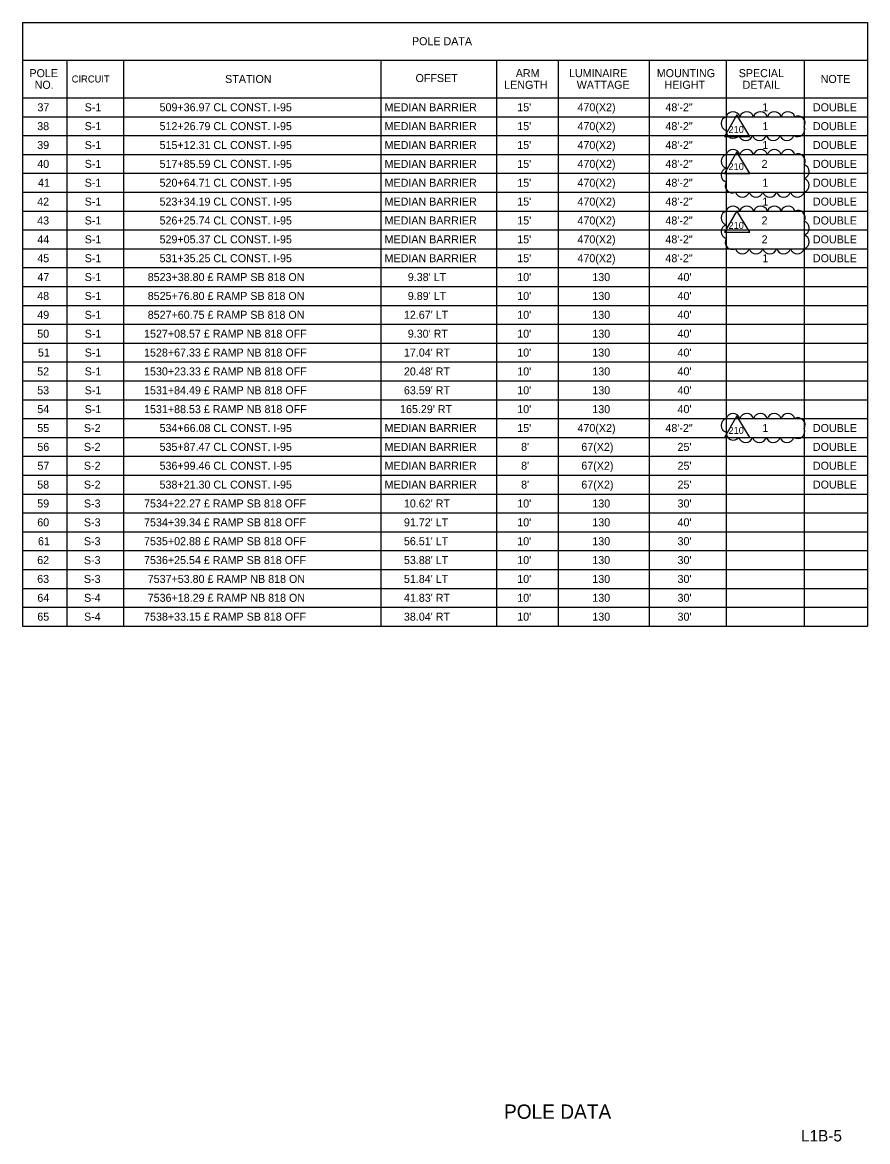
# Model space of a CAD drawing. Extents: x -816.7 to -800.7, y -2197.9 to -2187.9.
# Drawn here: x -808.09 to -800.7, y -2197.64 to -2187.86 of the extents above; entities that cross this region are included whole.
import ezdxf

# ---------------------------------------------------------------- set-up
doc = ezdxf.new("R2010")
doc.units = 0
for name, color, linetype in [('ScratchEle_dp', 7, 'Continuous'), ('SumBoxBorder_dp', 7, 'Continuous'), ('SumBoxLines_dp', 7, 'Continuous'), ('SumBoxLinesMin_dp', 7, 'Continuous'), ('TextLabel', 7, 'Continuous'), ('TextMisc', 7, 'Continuous'), ('TextShtNo', 7, 'Continuous')]:
    doc.layers.add(name, color=color, linetype=linetype)

msp = doc.modelspace()

# ---------------------------------------------------------------- linework, layer by layer
at = {"layer": 'ScratchEle_dp'}
for points in [[(-801.8411, -2188.6653), (-801.9488, -2188.8534), (-801.7282, -2188.8534)], [(-801.8411, -2188.9897), (-801.9488, -2189.1778), (-801.7282, -2189.1778)], [(-801.8411, -2189.504), (-801.9488, -2189.6921), (-801.7282, -2189.6921)], [(-801.8411, -2191.2972), (-801.9488, -2191.4853), (-801.7282, -2191.4853)]]:
    msp.add_lwpolyline(points, close=True, dxfattribs=at)
for centre, radius, start, end in [((-801.8748, -2188.7001), 0.0629, 17.5, 162.5), ((-801.7548, -2188.7001), 0.0629, 17.5, 162.5), ((-801.6348, -2188.7001), 0.0629, 17.5, 162.5), ((-801.5147, -2188.7001), 0.0629, 17.5, 162.5), ((-801.3947, -2188.7001), 0.0629, 17.5, 162.5), ((-801.9159, -2188.7412), 0.0629, 107.5, 252.5), ((-801.3073, -2188.7378), 0.0629, 330.87934, 115.87934), ((-801.8721, -2188.8062), 0.0629, 175.48211, 320.48211), ((-801.3102, -2188.7929), 0.0629, 237.99061, 22.99061), ((-801.7636, -2188.8273), 0.0629, 197.5, 342.5), ((-801.6436, -2188.8273), 0.0629, 197.5, 342.5), ((-801.5236, -2188.8273), 0.0629, 197.5, 342.5), ((-801.4035, -2188.8273), 0.0629, 197.5, 342.5), ((-801.9159, -2189.0714), 0.0631, 107.5, 252.5), ((-801.8747, -2189.0302), 0.0631, 17.5, 162.5), ((-801.7543, -2189.0302), 0.0631, 17.5, 162.5), ((-801.6339, -2189.0302), 0.0631, 17.5, 162.5), ((-801.5136, -2189.0302), 0.0631, 17.5, 162.5), ((-801.3932, -2189.0302), 0.0631, 17.5, 162.5), ((-801.3067, -2189.0686), 0.0631, 329.60153, 114.60153), ((-801.2713, -2189.1607), 0.0631, 287.5, 72.5), ((-801.9159, -2189.1918), 0.0631, 107.5, 252.5), ((-801.2713, -2189.281), 0.0631, 287.5, 72.5), ((-801.8804, -2189.2839), 0.0631, 149.60153, 294.60153), ((-801.794, -2189.3222), 0.0631, 197.5, 342.5), ((-801.6736, -2189.3222), 0.0631, 197.5, 342.5), ((-801.5533, -2189.3222), 0.0631, 197.5, 342.5), ((-801.4329, -2189.3222), 0.0631, 197.5, 342.5), ((-801.3125, -2189.3222), 0.0631, 197.5, 342.5), ((-801.9159, -2189.5664), 0.0631, 107.5, 252.5), ((-801.8747, -2189.5252), 0.0631, 17.5, 162.5), ((-801.7543, -2189.5252), 0.0631, 17.5, 162.5), ((-801.6339, -2189.5252), 0.0631, 17.5, 162.5), ((-801.5136, -2189.5252), 0.0631, 17.5, 162.5), ((-801.3932, -2189.5252), 0.0631, 17.5, 162.5), ((-801.3067, -2189.5636), 0.0631, 329.60153, 114.60153), ((-801.2713, -2189.6557), 0.0631, 287.5, 72.5), ((-801.9159, -2189.6868), 0.0631, 107.5, 252.5), ((-801.2713, -2189.776), 0.0631, 287.5, 72.5), ((-801.8804, -2189.7789), 0.0631, 149.60153, 294.60153), ((-801.794, -2189.8172), 0.0631, 197.5, 342.5), ((-801.6736, -2189.8172), 0.0631, 197.5, 342.5), ((-801.5533, -2189.8172), 0.0631, 197.5, 342.5), ((-801.4329, -2189.8172), 0.0631, 197.5, 342.5), ((-801.3125, -2189.8172), 0.0631, 197.5, 342.5), ((-801.8748, -2191.3401), 0.0629, 17.5, 162.5), ((-801.7548, -2191.3401), 0.0629, 17.5, 162.5), ((-801.6348, -2191.3401), 0.0629, 17.5, 162.5), ((-801.5147, -2191.3401), 0.0629, 17.5, 162.5), ((-801.3947, -2191.3401), 0.0629, 17.5, 162.5), ((-801.9159, -2191.3812), 0.0629, 107.5, 252.5), ((-801.3073, -2191.3778), 0.0629, 330.87934, 115.87934), ((-801.8721, -2191.4462), 0.0629, 175.48211, 320.48211), ((-801.3102, -2191.4329), 0.0629, 237.99061, 22.99061), ((-801.7636, -2191.4673), 0.0629, 197.5, 342.5), ((-801.6436, -2191.4673), 0.0629, 197.5, 342.5), ((-801.5236, -2191.4673), 0.0629, 197.5, 342.5), ((-801.4035, -2191.4673), 0.0629, 197.5, 342.5)]:
    msp.add_arc(centre, radius, start, end, dxfattribs=at)
at = {"layer": 'SumBoxBorder_dp'}
for p, q in [((-808.0923, -2187.8562), (-800.6973, -2187.8562)), ((-808.0923, -2187.8562), (-808.0923, -2193.1362)), ((-800.6973, -2187.8562), (-800.6973, -2193.1362)), ((-808.0923, -2188.1862), (-800.6973, -2188.1862)), ((-808.0923, -2188.1862), (-800.6973, -2188.1862)), ((-808.0923, -2193.1362), (-800.6973, -2193.1362)), ((-808.0923, -2193.1362), (-800.6973, -2193.1362))]:
    msp.add_line(p, q, dxfattribs=at)
at = {"layer": 'SumBoxLines_dp'}
for p, q in [((-807.7023, -2188.1862), (-807.7023, -2193.1362)), ((-807.7023, -2188.1862), (-807.7023, -2193.1362)), ((-807.2073, -2188.1862), (-807.2073, -2191.9812)), ((-807.2073, -2188.1862), (-807.2073, -2193.1362)), ((-804.9573, -2188.1862), (-804.9573, -2191.4862)), ((-804.9573, -2188.1862), (-804.9573, -2193.1362)), ((-803.9448, -2188.1862), (-803.9448, -2193.1362)), ((-803.9448, -2188.1862), (-803.9448, -2193.1362)), ((-803.4048, -2188.1862), (-803.4048, -2191.9812)), ((-803.4048, -2188.1862), (-803.4048, -2193.1362)), ((-802.6098, -2188.1862), (-802.6098, -2193.1362)), ((-802.6098, -2188.1862), (-802.6098, -2193.1362)), ((-801.9348, -2188.1862), (-801.9348, -2193.1362)), ((-801.9348, -2188.1862), (-801.9348, -2193.1362)), ((-801.2523, -2188.1862), (-801.2523, -2193.1362)), ((-808.0923, -2188.5162), (-800.6973, -2188.5162)), ((-804.9573, -2191.6512), (-804.9573, -2193.1362)), ((-807.2073, -2192.1462), (-807.2073, -2192.3112)), ((-803.4048, -2192.1462), (-803.4048, -2193.1362)), ((-807.2073, -2192.4762), (-807.2073, -2192.6412)), ((-807.2073, -2192.8062), (-807.2073, -2193.1362))]:
    msp.add_line(p, q, dxfattribs=at)
at = {"layer": 'SumBoxLinesMin_dp'}
for p, q in [((-808.0923, -2188.5162), (-800.6973, -2188.5162)), ((-808.0923, -2188.6812), (-800.6973, -2188.6812)), ((-808.0923, -2188.6812), (-800.6973, -2188.6812)), ((-808.0923, -2188.8462), (-800.6973, -2188.8462)), ((-808.0923, -2188.8462), (-800.6973, -2188.8462)), ((-808.0923, -2189.0112), (-800.6973, -2189.0112)), ((-808.0923, -2189.0112), (-800.6973, -2189.0112)), ((-808.0923, -2189.1762), (-800.6973, -2189.1762)), ((-808.0923, -2189.1762), (-800.6973, -2189.1762)), ((-808.0923, -2189.3412), (-800.6973, -2189.3412)), ((-808.0923, -2189.3412), (-800.6973, -2189.3412)), ((-808.0923, -2189.5062), (-800.6973, -2189.5062)), ((-808.0923, -2189.5062), (-800.6973, -2189.5062)), ((-808.0923, -2189.6712), (-800.6973, -2189.6712)), ((-808.0923, -2189.6712), (-800.6973, -2189.6712)), ((-808.0923, -2189.8362), (-800.6973, -2189.8362)), ((-808.0923, -2189.8362), (-800.6973, -2189.8362)), ((-808.0923, -2190.0012), (-800.6973, -2190.0012)), ((-808.0923, -2190.0012), (-800.6973, -2190.0012)), ((-808.0923, -2190.1662), (-800.6973, -2190.1662)), ((-808.0923, -2190.1662), (-800.6973, -2190.1662)), ((-808.0923, -2190.3312), (-800.6973, -2190.3312)), ((-808.0923, -2190.3312), (-800.6973, -2190.3312)), ((-808.0923, -2190.4962), (-800.6973, -2190.4962)), ((-808.0923, -2190.4962), (-800.6973, -2190.4962)), ((-808.0923, -2190.6612), (-800.6973, -2190.6612)), ((-808.0923, -2190.6612), (-800.6973, -2190.6612)), ((-808.0923, -2190.8262), (-800.6973, -2190.8262)), ((-808.0923, -2190.8262), (-800.6973, -2190.8262)), ((-808.0923, -2190.9912), (-800.6973, -2190.9912)), ((-808.0923, -2190.9912), (-800.6973, -2190.9912)), ((-808.0923, -2191.1562), (-800.6973, -2191.1562)), ((-808.0923, -2191.1562), (-800.6973, -2191.1562)), ((-808.0923, -2191.3212), (-800.6973, -2191.3212)), ((-808.0923, -2191.3212), (-800.6973, -2191.3212)), ((-808.0923, -2191.4862), (-800.6973, -2191.4862)), ((-808.0923, -2191.4862), (-800.6973, -2191.4862)), ((-808.0923, -2191.6512), (-807.2073, -2191.6512)), ((-808.0923, -2191.6512), (-800.6973, -2191.6512)), ((-804.9573, -2191.6512), (-800.6973, -2191.6512)), ((-808.0923, -2191.8162), (-800.6973, -2191.8162)), ((-808.0923, -2191.8162), (-800.6973, -2191.8162)), ((-808.0923, -2191.9812), (-800.6973, -2191.9812)), ((-808.0923, -2191.9812), (-800.6973, -2191.9812)), ((-808.0923, -2192.1462), (-807.7023, -2192.1462)), ((-808.0923, -2192.1462), (-800.6973, -2192.1462)), ((-807.2073, -2192.1462), (-803.9448, -2192.1462)), ((-803.4048, -2192.1462), (-800.6973, -2192.1462)), ((-808.0923, -2192.3112), (-800.6973, -2192.3112)), ((-808.0923, -2192.3112), (-800.6973, -2192.3112)), ((-808.0923, -2192.4762), (-807.7023, -2192.4762)), ((-808.0923, -2192.4762), (-800.6973, -2192.4762)), ((-804.9573, -2192.4762), (-800.6973, -2192.4762)), ((-808.0923, -2192.6412), (-800.6973, -2192.6412)), ((-808.0923, -2192.6412), (-800.6973, -2192.6412)), ((-808.0923, -2192.8062), (-807.7023, -2192.8062)), ((-808.0923, -2192.8062), (-800.6973, -2192.8062)), ((-804.9573, -2192.8062), (-800.6973, -2192.8062)), ((-808.0923, -2192.9712), (-800.6973, -2192.9712)), ((-808.0923, -2192.9712), (-800.6973, -2192.9712))]:
    msp.add_line(p, q, dxfattribs=at)

# ---------------------------------------------------------------- texts
at = {"layer": 'ScratchEle_dp'}
for p in [(-801.9143, -2188.8232), (-801.9143, -2189.1477), (-801.9143, -2189.6619), (-801.9143, -2191.4552)]:
    msp.add_text('210', height=0.05998, rotation=0, dxfattribs=at).set_placement(p)
at = {"layer": 'TextLabel'}
for s, height, p in [('POLE DATA', 0.07, (-804.6838, -2188.0562)), ('POLE', 0.07, (-808.0306, -2188.3352)), ('CIRCUIT', 0.06125, (-807.6608, -2188.3818)), ('STATION', 0.07, (-806.3182, -2188.3862)), ('OFFSET', 0.07, (-804.6526, -2188.3782)), ('ARM', 0.07, (-803.7754, -2188.3352)), ('LUMINAIRE', 0.07, (-803.31, -2188.3352)), ('MOUNTING', 0.07, (-802.542, -2188.3352)), ('SPECIAL', 0.07, (-801.825, -2188.3352)), ('NOTE', 0.07, (-801.1081, -2188.3862)), ('NO.', 0.07, (-807.985, -2188.4372)), ('LENGTH', 0.07, (-803.8768, -2188.4372)), ('WATTAGE', 0.07, (-803.2423, -2188.4372)), ('HEIGHT', 0.07, (-802.4738, -2188.4372)), ('DETAIL', 0.07, (-801.7911, -2188.4372)), ('37', 0.07, (-807.9606, -2188.6337)), ('S-1', 0.07, (-807.5473, -2188.6337)), ('509+36.97 CL CONST. I-95', 0.07, (-806.8921, -2188.6337)), ('MEDIAN BARRIER', 0.07, (-804.9232, -2188.6337)), ("15'", 0.07, (-803.7628, -2188.6337)), ('470(X2)', 0.07, (-803.2358, -2188.6337)), ('48\'-2"', 0.07, (-802.4663, -2188.6337)), ('1', 0.07, (-801.6183, -2188.6337)), ('DOUBLE', 0.07, (-801.1759, -2188.6337)), ('38', 0.07, (-807.9624, -2188.7987)), ('S-1', 0.07, (-807.5473, -2188.7987)), ('512+26.79 CL CONST. I-95', 0.07, (-806.8921, -2188.7987)), ('MEDIAN BARRIER', 0.07, (-804.9232, -2188.7987)), ("15'", 0.07, (-803.7628, -2188.7987)), ('470(X2)', 0.07, (-803.2358, -2188.7987)), ('48\'-2"', 0.07, (-802.4663, -2188.7987)), ('1', 0.07, (-801.6183, -2188.7987)), ('DOUBLE', 0.07, (-801.1759, -2188.7987)), ('39', 0.07, (-807.9622, -2188.9637)), ('S-1', 0.07, (-807.5473, -2188.9637)), ('515+12.31 CL CONST. I-95', 0.07, (-806.8921, -2188.9637)), ('MEDIAN BARRIER', 0.07, (-804.9232, -2188.9637)), ("15'", 0.07, (-803.7628, -2188.9637)), ('470(X2)', 0.07, (-803.2358, -2188.9637)), ('48\'-2"', 0.07, (-802.4663, -2188.9637)), ('1', 0.07, (-801.6183, -2188.9637)), ('DOUBLE', 0.07, (-801.1759, -2188.9637)), ('40', 0.07, (-807.9621, -2189.1287)), ('S-1', 0.07, (-807.5473, -2189.1287)), ('517+85.59 CL CONST. I-95', 0.07, (-806.8921, -2189.1287)), ('MEDIAN BARRIER', 0.07, (-804.9232, -2189.1287)), ("15'", 0.07, (-803.7628, -2189.1287)), ('470(X2)', 0.07, (-803.2358, -2189.1287)), ('48\'-2"', 0.07, (-802.4663, -2189.1287)), ('2', 0.07, (-801.625, -2189.1287)), ('DOUBLE', 0.07, (-801.1759, -2189.1287)), ('41', 0.07, (-807.9559, -2189.2937)), ('S-1', 0.07, (-807.5473, -2189.2937)), ('520+64.71 CL CONST. I-95', 0.07, (-806.8921, -2189.2937)), ('MEDIAN BARRIER', 0.07, (-804.9232, -2189.2937)), ("15'", 0.07, (-803.7628, -2189.2937)), ('470(X2)', 0.07, (-803.2358, -2189.2937)), ('48\'-2"', 0.07, (-802.4663, -2189.2937)), ('1', 0.07, (-801.6183, -2189.2937)), ('DOUBLE', 0.07, (-801.1759, -2189.2937)), ('42', 0.07, (-807.9626, -2189.4587)), ('S-1', 0.07, (-807.5473, -2189.4587)), ('523+34.19 CL CONST. I-95', 0.07, (-806.8921, -2189.4587)), ('MEDIAN BARRIER', 0.07, (-804.9232, -2189.4587)), ("15'", 0.07, (-803.7628, -2189.4587)), ('470(X2)', 0.07, (-803.2358, -2189.4587)), ('48\'-2"', 0.07, (-802.4663, -2189.4587)), ('1', 0.07, (-801.6183, -2189.4587)), ('DOUBLE', 0.07, (-801.1759, -2189.4587)), ('43', 0.07, (-807.9627, -2189.6237)), ('S-1', 0.07, (-807.5473, -2189.6237)), ('526+25.74 CL CONST. I-95', 0.07, (-806.8921, -2189.6237)), ('MEDIAN BARRIER', 0.07, (-804.9232, -2189.6237)), ("15'", 0.07, (-803.7628, -2189.6237)), ('470(X2)', 0.07, (-803.2358, -2189.6237)), ('48\'-2"', 0.07, (-802.4663, -2189.6237)), ('2', 0.07, (-801.625, -2189.6237)), ('DOUBLE', 0.07, (-801.1759, -2189.6237)), ('470(X2)', 0.07, (-803.2358, -2189.7887)), ('44', 0.07, (-807.9613, -2189.7887)), ('S-1', 0.07, (-807.5473, -2189.7887)), ('529+05.37 CL CONST. I-95', 0.07, (-806.8921, -2189.7887)), ('MEDIAN BARRIER', 0.07, (-804.9232, -2189.7887)), ("15'", 0.07, (-803.7628, -2189.7887)), ('48\'-2"', 0.07, (-802.4663, -2189.7887)), ('2', 0.07, (-801.625, -2189.7887)), ('DOUBLE', 0.07, (-801.1759, -2189.7887)), ('45', 0.07, (-807.9618, -2189.9537)), ('S-1', 0.07, (-807.5473, -2189.9537)), ('531+35.25 CL CONST. I-95', 0.07, (-806.8921, -2189.9537)), ('MEDIAN BARRIER', 0.07, (-804.9232, -2189.9537)), ("15'", 0.07, (-803.7628, -2189.9537)), ('470(X2)', 0.07, (-803.2358, -2189.9537)), ('48\'-2"', 0.07, (-802.4663, -2189.9537)), ('1', 0.07, (-801.6183, -2189.9537)), ('DOUBLE', 0.07, (-801.1759, -2189.9537)), ('47', 0.07, (-807.9606, -2190.1187)), ('S-1', 0.07, (-807.5473, -2190.1187)), ('8523+38.80 £ RAMP SB 818 ON', 0.07, (-806.9957, -2190.1187)), ("9.38' LT", 0.07, (-804.7203, -2190.1187)), ("10'", 0.07, (-803.7628, -2190.1187)), ('130', 0.07, (-803.1059, -2190.1187)), ("40'", 0.07, (-802.3603, -2190.1187)), ('48', 0.07, (-807.9624, -2190.2837)), ('S-1', 0.07, (-807.5473, -2190.2837)), ('8525+76.80 £ RAMP SB 818 ON', 0.07, (-806.9957, -2190.2837)), ("9.89' LT", 0.07, (-804.7203, -2190.2837)), ("10'", 0.07, (-803.7628, -2190.2837)), ('130', 0.07, (-803.1059, -2190.2837)), ("40'", 0.07, (-802.3603, -2190.2837)), ('49', 0.07, (-807.9622, -2190.4487)), ('S-1', 0.07, (-807.5473, -2190.4487)), ('8527+60.75 £ RAMP SB 818 ON', 0.07, (-806.9957, -2190.4487)), ("12.67' LT", 0.07, (-804.7542, -2190.4487)), ("10'", 0.07, (-803.7628, -2190.4487)), ('130', 0.07, (-803.1059, -2190.4487)), ("40'", 0.07, (-802.3603, -2190.4487)), ('50', 0.07, (-807.9621, -2190.6137)), ('S-1', 0.07, (-807.5473, -2190.6137)), ('1527+08.57 £ RAMP NB 818 OFF', 0.07, (-807.0277, -2190.6137)), ("9.30' RT", 0.07, (-804.7203, -2190.6137)), ("10'", 0.07, (-803.7628, -2190.6137)), ('130', 0.07, (-803.1059, -2190.6137)), ("40'", 0.07, (-802.3603, -2190.6137)), ('51', 0.07, (-807.9559, -2190.7787)), ('S-1', 0.07, (-807.5473, -2190.7787)), ('1528+67.33 £ RAMP NB 818 OFF', 0.07, (-807.0277, -2190.7787)), ("17.04' RT", 0.07, (-804.7542, -2190.7787)), ("10'", 0.07, (-803.7628, -2190.7787)), ('130', 0.07, (-803.1059, -2190.7787)), ("40'", 0.07, (-802.3603, -2190.7787)), ('52', 0.07, (-807.9626, -2190.9437)), ('S-1', 0.07, (-807.5473, -2190.9437)), ('1530+23.33 £ RAMP NB 818 OFF', 0.07, (-807.0277, -2190.9437)), ("20.48' RT", 0.07, (-804.7542, -2190.9437)), ("10'", 0.07, (-803.7628, -2190.9437)), ('130', 0.07, (-803.1059, -2190.9437)), ("40'", 0.07, (-802.3603, -2190.9437)), ('53', 0.07, (-807.9627, -2191.1087)), ('S-1', 0.07, (-807.5473, -2191.1087)), ('1531+84.49 £ RAMP NB 818 OFF', 0.07, (-807.0277, -2191.1087)), ("63.59' RT", 0.07, (-804.7542, -2191.1087)), ("10'", 0.07, (-803.7628, -2191.1087)), ('130', 0.07, (-803.1059, -2191.1087)), ("40'", 0.07, (-802.3603, -2191.1087)), ('54', 0.07, (-807.9613, -2191.2737)), ('S-1', 0.07, (-807.5473, -2191.2737)), ('1531+88.53 £ RAMP NB 818 OFF', 0.07, (-807.0277, -2191.2737)), ("165.29' RT", 0.07, (-804.7881, -2191.2737)), ("10'", 0.07, (-803.7628, -2191.2737)), ('130', 0.07, (-803.1059, -2191.2737)), ("40'", 0.07, (-802.3603, -2191.2737)), ('55', 0.07, (-807.9618, -2191.4387)), ('S-2', 0.07, (-807.554, -2191.4387)), ('534+66.08 CL CONST. I-95', 0.07, (-806.8921, -2191.4387)), ('MEDIAN BARRIER', 0.07, (-804.9232, -2191.4387)), ("15'", 0.07, (-803.7628, -2191.4387)), ('470(X2)', 0.07, (-803.2358, -2191.4387)), ('48\'-2"', 0.07, (-802.4663, -2191.4387)), ('1', 0.07, (-801.6183, -2191.4387)), ('DOUBLE', 0.07, (-801.1759, -2191.4387)), ('56', 0.07, (-807.9612, -2191.6037)), ('S-2', 0.07, (-807.554, -2191.6037)), ('535+87.47 CL CONST. I-95', 0.07, (-806.8921, -2191.6037)), ('MEDIAN BARRIER', 0.07, (-804.9232, -2191.6037)), ("8'", 0.07, (-803.7289, -2191.6037)), ('67(X2)', 0.07, (-803.202, -2191.6037)), ("25'", 0.07, (-802.3603, -2191.6037)), ('DOUBLE', 0.07, (-801.1759, -2191.6037)), ('57', 0.07, (-807.9606, -2191.7687)), ('S-2', 0.07, (-807.554, -2191.7687)), ('536+99.46 CL CONST. I-95', 0.07, (-806.8921, -2191.7687)), ('MEDIAN BARRIER', 0.07, (-804.9232, -2191.7687)), ("8'", 0.07, (-803.7289, -2191.7687)), ('67(X2)', 0.07, (-803.202, -2191.7687)), ("25'", 0.07, (-802.3603, -2191.7687)), ('DOUBLE', 0.07, (-801.1759, -2191.7687)), ('58', 0.07, (-807.9624, -2191.9337)), ('S-2', 0.07, (-807.554, -2191.9337)), ('538+21.30 CL CONST. I-95', 0.07, (-806.8921, -2191.9337)), ('MEDIAN BARRIER', 0.07, (-804.9232, -2191.9337)), ("8'", 0.07, (-803.7289, -2191.9337)), ('67(X2)', 0.07, (-803.202, -2191.9337)), ("25'", 0.07, (-802.3603, -2191.9337)), ('DOUBLE', 0.07, (-801.1759, -2191.9337)), ('59', 0.07, (-807.9622, -2192.0987)), ('S-3', 0.07, (-807.554, -2192.0987)), ('7534+22.27 £ RAMP SB 818 OFF', 0.07, (-807.0277, -2192.0987)), ("10.62' RT", 0.07, (-804.7542, -2192.0987)), ("10'", 0.07, (-803.7628, -2192.0987)), ('130', 0.07, (-803.1059, -2192.0987)), ("30'", 0.07, (-802.3603, -2192.0987)), ('60', 0.07, (-807.9621, -2192.2637)), ('S-3', 0.07, (-807.554, -2192.2637)), ('7534+39.34 £ RAMP SB 818 OFF', 0.07, (-807.0277, -2192.2637)), ("91.72' LT", 0.07, (-804.7542, -2192.2637)), ("10'", 0.07, (-803.7628, -2192.2637)), ('130', 0.07, (-803.1059, -2192.2637)), ("40'", 0.07, (-802.3603, -2192.2637)), ('61', 0.07, (-807.9559, -2192.4287)), ('S-3', 0.07, (-807.554, -2192.4287)), ('7535+02.88 £ RAMP SB 818 OFF', 0.07, (-807.0277, -2192.4287)), ("56.51' LT", 0.07, (-804.7542, -2192.4287)), ("10'", 0.07, (-803.7628, -2192.4287)), ('130', 0.07, (-803.1059, -2192.4287)), ("30'", 0.07, (-802.3603, -2192.4287)), ('62', 0.07, (-807.9626, -2192.5937)), ('S-3', 0.07, (-807.554, -2192.5937)), ('7536+25.54 £ RAMP SB 818 OFF', 0.07, (-807.0277, -2192.5937)), ("53.88' LT", 0.07, (-804.7542, -2192.5937)), ("10'", 0.07, (-803.7628, -2192.5937)), ('130', 0.07, (-803.1059, -2192.5937)), ("30'", 0.07, (-802.3603, -2192.5937)), ('63', 0.07, (-807.9627, -2192.7587)), ('S-3', 0.07, (-807.554, -2192.7587)), ('7537+53.80 £ RAMP NB 818 ON', 0.07, (-806.9957, -2192.7587)), ("51.84' LT", 0.07, (-804.7542, -2192.7587)), ("10'", 0.07, (-803.7628, -2192.7587)), ('130', 0.07, (-803.1059, -2192.7587)), ("30'", 0.07, (-802.3603, -2192.7587)), ('64', 0.07, (-807.9613, -2192.9237)), ('S-4', 0.07, (-807.5526, -2192.9237)), ('7536+18.29 £ RAMP NB 818 ON', 0.07, (-806.9957, -2192.9237)), ("41.83' RT", 0.07, (-804.7542, -2192.9237)), ("10'", 0.07, (-803.7628, -2192.9237)), ('130', 0.07, (-803.1059, -2192.9237)), ("30'", 0.07, (-802.3603, -2192.9237)), ('65', 0.07, (-807.9618, -2193.0887)), ('S-4', 0.07, (-807.5526, -2193.0887)), ('7538+33.15 £ RAMP SB 818 OFF', 0.07, (-807.0277, -2193.0887)), ("38.04' RT", 0.07, (-804.7542, -2193.0887)), ("10'", 0.07, (-803.7628, -2193.0887)), ('130', 0.07, (-803.1059, -2193.0887)), ("30'", 0.07, (-802.3603, -2193.0887))]:
    msp.add_text(s, height=height, dxfattribs=at).set_placement(p)
at = {"layer": 'TextMisc'}
msp.add_text('POLE DATA', height=0.125, dxfattribs=at).set_placement((-803.8787, -2197.445))
at = {"layer": 'TextShtNo'}
msp.add_text('L1B-5  ', height=0.1, dxfattribs=at).set_placement((-801.2789, -2197.6434))

doc.saveas('drawing.dxf')
